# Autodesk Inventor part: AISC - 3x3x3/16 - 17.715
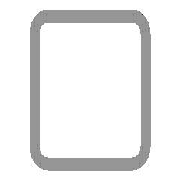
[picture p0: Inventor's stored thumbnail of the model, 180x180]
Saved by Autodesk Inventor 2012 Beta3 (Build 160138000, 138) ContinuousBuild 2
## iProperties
_CCFamilyMember: 9
_CCFamilyDisplayName: ANSI AISC (Square) - Tube
_FrameMemberDoc: Frame Member File
_Version: 15.0.0
_GetPNFromCC: 1
Created: 2010-11
Part Number: AISC - 3x3x3/16 - 17.715
Material: Steel, Mild
Description: Tube
Document SubType Name: Modeling
Standard: ANSI
Designer: Beta-8540w
Standards Organization: ANSI
Language: en-US
Size Designation: 3x3x3/16
Categories: <MemberInstance><Categories><Category DisplayName="Structural Shapes" InternalName="089c4875-fa83-4c05-b084-43b9cc11f5ed" Mnemonic="GRDR"><CategoryParameter Dis
Stock Number: 3x3x3/16
Density: 7.86 g/cm^3
IsCustomPart: 1
G_L: 17.715 in
G_W: 3.000 in
G_H: 3.000 in
Author: Beta-8540w
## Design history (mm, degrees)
node "Start plane"
node "End plane"
sketch "Sketch"
  geometry: L1 (-38.1, -28.575)-(-38.1, 28.575); L2 (-28.575, 38.1)-(28.575, 38.1); L3 (38.1, 28.575)-(38.1, -28.575); L4 (28.575, -38.1)-(-28.575, -38.1); L5 (-28.575, 33.337)-(28.575, 33.338); L6 (33.338, 28.575)-(33.338, -28.575); L7 (28.575, -33.337)-(-28.575, -33.338); L8 (-33.338, -28.575)-(-33.338, 28.575); L9 (0, 56.102)-(0, -56.102) reference; L10 (-56.102, 0)-(56.102, 0) reference; A1 r 9.525 centre (-28.575, -28.575) between (-38.1, -28.575) and (-28.575, -38.1); A2 r 9.525 centre (-28.575, 28.575) between (-28.575, 38.1) and (-38.1, 28.575); A3 r 9.525 centre (28.575, 28.575) between (38.1, 28.575) and (28.575, 38.1); A4 r 9.525 centre (28.575, -28.575) between (28.575, -38.1) and (38.1, -28.575); A5 r 4.763 centre (-28.575, 28.575) between (-28.575, 33.337) and (-33.338, 28.575); A6 r 4.763 centre (28.575, 28.575) between (33.338, 28.575) and (28.575, 33.338); A7 r 4.763 centre (28.575, -28.575) between (28.575, -33.337) and (33.338, -28.575); A8 r 4.763 centre (-28.575, -28.575) between (-33.338, -28.575) and (-28.575, -33.338)
  constraints: 16 end point, 16 point on circle, 8 centre point, 8 tangent, 4 parallel, 3 equal radius, 2 perpendicular, 7 other
  dimensions: "d10" = 76.2 distance between parallel lines of L2 L4 (= G_H); "d11" = 76.2 distance between parallel lines of L1 L3 (= G_W); "d12" = 4.7625 distance between parallel lines of L3 L6 (= G_T); "d15" = 38.1 distance between parallel lines of L2 L10 (= 0.5 x d10); "d16" = 38.1 distance between parallel lines of L9 L3 (= 0.5 x d11); "d17" = 9.525 radius of A1 (= G_IR)
extrude "Body" new body sketch "Sketch" stored distance "d3" = 449.97309 (= G_L); taper "d4" = 0 deg
node "Driven Length"
  sketch "Sketch3"
    geometry: L1 (0, 0)-(10, 0) reference
    constraints: 2 end point, 1 horizontal
  workplane "Work Plane3"
  sketch "Sketch4"
    geometry: L1 (-2, 0)-(12, 0) reference; L2 (-2, 449.973)-(12, 449.973) reference
    dimensions: "d19" = 449.97309 distance between parallel lines of L1 L2 (derived)
body "Solid1"
other parameters: "G_W" = 76.2 [user parameter; used in 1 equation term], "G_H" = 76.2 [user parameter; used in 1 equation term], "G_T" = 4.7625 [user parameter; used in 1 equation term], "G_IR" = 9.525 [user parameter; used in 1 equation term], "G_L" = 449.97309 (= d19) [user parameter; used in 1 equation term], "G_OFFSET_START" = 0 [user parameter; used in 1 equation term], "G_OFFSET_END" = 0 [user parameter; used in 1 equation term], "d13" = 0 (computed from G_OFFSET_START), "d14" = 449.97309 (= G_OFFSET_END + B_L), "B_L" = 449.97309 [user parameter; used in 1 equation term], "d18" = 90 deg
